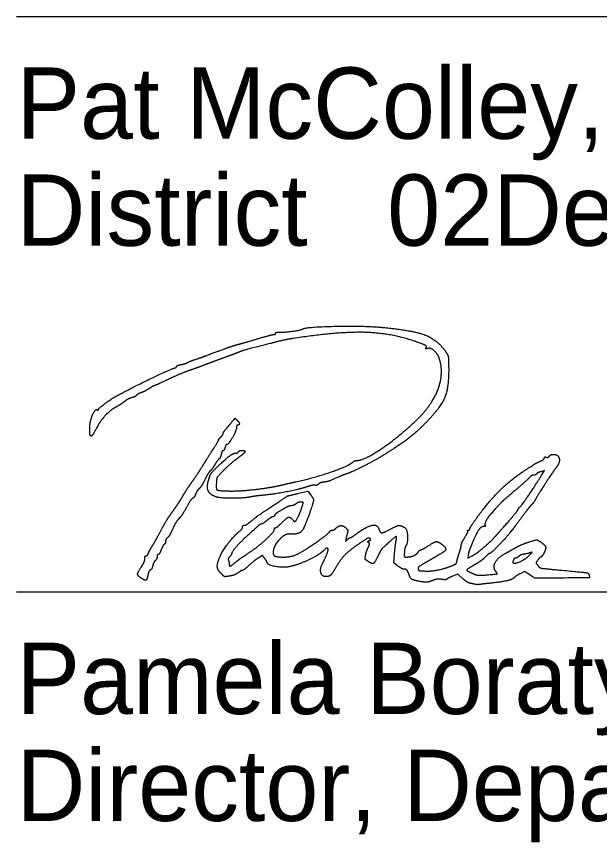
# Model space of a CAD drawing. Extents: x 0 to 34, y 0 to 22.
# Drawn here: x 24.528 to 25.673, y 7.305 to 8.926 of the extents above; entities that cross this region are included whole.
import ezdxf

# ---------------------------------------------------------------- set-up
doc = ezdxf.new("R2010")
doc.units = 0
doc.layers.add('SH_Data', color=7, linetype='Continuous')
doc.layers.add('SH_Text', color=7, linetype='Continuous')

msp = doc.modelspace()

# ---------------------------------------------------------------- linework, layer by layer
at = {"layer": 'SH_Data'}
for p, q in [((24.5279, 8.9262), (28.0279, 8.9262)), ((24.5279, 7.7968), (28.0279, 7.7968))]:
    msp.add_line(p, q, dxfattribs=at)
at = {"layer": 'SH_Text'}
for points in [[(25.5597, 8.0263), (25.5651, 8.0352), (25.5577, 8.0326)], [(25.0824, 7.9901), (25.1004, 7.9942), (25.1051, 7.988)], [(25.2773, 7.8473), (25.269, 7.8536), (25.2704, 7.8707)], [(25.4153, 7.8693), (25.4143, 7.8628), (25.4229, 7.8673)], [(25.5361, 7.83), (25.5255, 7.8368), (25.5171, 7.8323)], [(25.4043, 7.823), (25.3951, 7.8313), (25.3845, 7.8272)]]:
    msp.add_lwpolyline(points, dxfattribs=at)
for points in [[(25.033, 8.3018), (25.0351, 8.3018), (25.0368, 8.3029), (25.0368, 8.3043)], [(25.0368, 8.3043), (25.0368, 8.3056), (25.0408, 8.3066), (25.0458, 8.3065)], [(25.0458, 8.3065), (25.0554, 8.3062), (25.0864, 8.3106), (25.0898, 8.3127)], [(25.3205, 8.285), (25.2699, 8.304), (25.1619, 8.308), (25.0716, 8.2942)], [(25.0898, 8.3127), (25.0966, 8.3169), (25.2136, 8.3192), (25.248, 8.3158)], [(25.248, 8.3158), (25.3072, 8.31), (25.3548, 8.2917), (25.3706, 8.2686)], [(24.9612, 8.282), (24.9665, 8.2833), (24.9839, 8.2883), (25, 8.2931)], [(25, 8.2931), (25.0161, 8.2979), (25.031, 8.3018), (25.033, 8.3018)], [(25.0716, 8.2942), (25.0623, 8.2928), (25.0424, 8.2885), (25.0272, 8.2845)], [(24.8808, 8.2535), (24.8955, 8.2586), (24.9019, 8.261), (24.9372, 8.2741)], [(24.9372, 8.2741), (24.9451, 8.2771), (24.9559, 8.2806), (24.9612, 8.282)], [(25.0272, 8.2845), (24.9762, 8.2714), (24.9719, 8.2701), (24.9612, 8.2658)], [(25.3328, 8.2764), (25.3338, 8.2789), (25.3303, 8.2813), (25.3205, 8.285)], [(25.3352, 8.2743), (25.3326, 8.2733), (25.3319, 8.274), (25.3328, 8.2764)], [(25.3586, 8.2544), (25.3553, 8.2642), (25.3409, 8.2765), (25.3352, 8.2743)], [(24.9384, 8.2573), (24.9285, 8.2537), (24.9134, 8.2481), (24.9048, 8.2449)], [(24.9612, 8.2658), (24.9585, 8.2647), (24.9483, 8.2609), (24.9384, 8.2573)], [(25.3131, 8.1332), (25.344, 8.1627), (25.3679, 8.2262), (25.3586, 8.2544)], [(25.3706, 8.2686), (25.3755, 8.2614), (25.3764, 8.257), (25.3768, 8.2392)], [(24.837, 8.2357), (24.84, 8.2366), (24.8424, 8.2382), (24.8424, 8.2393)], [(24.8424, 8.2393), (24.8424, 8.2403), (24.8464, 8.242), (24.8514, 8.2429)], [(24.8514, 8.2429), (24.8563, 8.2438), (24.8615, 8.2454), (24.8628, 8.2464)], [(24.8628, 8.2464), (24.8641, 8.2473), (24.8722, 8.2506), (24.8808, 8.2535)], [(24.9048, 8.2449), (24.8962, 8.2416), (24.88, 8.2357), (24.8688, 8.2317)], [(25.3768, 8.2392), (25.3775, 8.1984), (25.3614, 8.1587), (25.332, 8.1288)], [(24.7248, 8.1814), (24.755, 8.1976), (24.8286, 8.2333), (24.837, 8.2357)], [(24.8688, 8.2317), (24.8576, 8.2278), (24.8372, 8.2192), (24.8236, 8.2127)], [(24.8236, 8.2127), (24.8099, 8.2063), (24.7983, 8.201), (24.7977, 8.201)], [(24.7877, 8.1953), (24.7828, 8.1922), (24.7761, 8.1888), (24.7729, 8.1878)], [(24.7977, 8.201), (24.7971, 8.201), (24.7927, 8.1984), (24.7877, 8.1953)], [(24.6888, 8.1547), (24.6888, 8.1569), (24.7142, 8.1757), (24.7248, 8.1814)], [(24.754, 8.1778), (24.7505, 8.1769), (24.7438, 8.1733), (24.7392, 8.1697)], [(24.7637, 8.1826), (24.7619, 8.1808), (24.7576, 8.1787), (24.754, 8.1778)], [(24.7729, 8.1878), (24.7697, 8.1868), (24.7655, 8.1844), (24.7637, 8.1826)], [(24.7233, 8.1594), (24.7129, 8.1541), (24.693, 8.1332), (24.6868, 8.1211)], [(24.7392, 8.1697), (24.7346, 8.1661), (24.7274, 8.1615), (24.7233, 8.1594)], [(24.6716, 8.1169), (24.6717, 8.1301), (24.6823, 8.1567), (24.6865, 8.1541)], [(24.6865, 8.1541), (24.6877, 8.1533), (24.6888, 8.1536), (24.6888, 8.1547)], [(24.939, 8.1158), (24.9575, 8.1379), (24.9568, 8.1374), (24.9609, 8.134)], [(24.9609, 8.134), (24.9652, 8.1304), (24.9661, 8.1242), (24.9624, 8.1242)], [(25.1964, 8.0546), (25.2105, 8.0546), (25.2786, 8.1005), (25.3131, 8.1332)], [(25.332, 8.1288), (25.3134, 8.1099), (25.281, 8.085), (25.2505, 8.0662)], [(24.673, 8.1032), (24.6722, 8.104), (24.6716, 8.1101), (24.6716, 8.1169)], [(24.6868, 8.1211), (24.6801, 8.1082), (24.6748, 8.1013), (24.673, 8.1032)], [(24.9336, 8.1072), (24.9336, 8.1084), (24.936, 8.1123), (24.939, 8.1158)], [(24.96, 8.1191), (24.96, 8.1135), (24.9441, 8.0858), (24.9409, 8.0858)], [(24.9624, 8.1242), (24.9611, 8.1242), (24.96, 8.1219), (24.96, 8.1191)], [(24.916, 8.0797), (24.9216, 8.0883), (24.9256, 8.0954), (24.925, 8.0954)], [(24.925, 8.0954), (24.9245, 8.0954), (24.9261, 8.0975), (24.9288, 8.1002)], [(24.9288, 8.1002), (24.9314, 8.1028), (24.9336, 8.1059), (24.9336, 8.1072)], [(24.894, 8.0447), (24.9006, 8.0553), (24.9105, 8.0711), (24.916, 8.0797)], [(24.9374, 8.0798), (24.9366, 8.0765), (24.9349, 8.0738), (24.9337, 8.0738)], [(24.9409, 8.0858), (24.9398, 8.0858), (24.9382, 8.0831), (24.9374, 8.0798)], [(24.9252, 8.0448), (24.9409, 8.0594), (24.9536, 8.069), (24.9576, 8.069)], [(24.93, 8.0666), (24.9291, 8.0626), (24.9274, 8.0588), (24.9261, 8.058)], [(24.9337, 8.0738), (24.9325, 8.0738), (24.9309, 8.0705), (24.93, 8.0666)], [(24.9576, 8.069), (24.9601, 8.069), (24.9628, 8.07), (24.9636, 8.0714)], [(24.9768, 8.0717), (24.9768, 8.0706), (24.97, 8.0647), (24.9618, 8.0586)], [(24.9636, 8.0714), (24.9654, 8.0743), (24.9768, 8.0746), (24.9768, 8.0717)], [(25.2505, 8.0662), (25.2313, 8.0543), (25.1901, 8.0333), (25.176, 8.0282)], [(25.5648, 8.0595), (25.5648, 8.061), (25.5663, 8.0617), (25.5682, 8.061)], [(25.5682, 8.061), (25.5701, 8.0602), (25.5729, 8.0612), (25.5745, 8.0631)], [(25.5745, 8.0631), (25.5761, 8.065), (25.5798, 8.0666), (25.5827, 8.0666)], [(25.5827, 8.0666), (25.5921, 8.0666), (25.5959, 8.0505), (25.5885, 8.0415)], [(24.8722, 8.0117), (24.8776, 8.0192), (24.8874, 8.034), (24.894, 8.0447)], [(24.9038, 8.0102), (24.9066, 8.0232), (24.9127, 8.0332), (24.9252, 8.0448)], [(24.9176, 8.0466), (24.9142, 8.0411), (24.9101, 8.0355), (24.9084, 8.0341)], [(24.9261, 8.058), (24.9248, 8.0572), (24.921, 8.0521), (24.9176, 8.0466)], [(24.9618, 8.0586), (24.9535, 8.0525), (24.941, 8.0416), (24.934, 8.0345)], [(25.0764, 8.0126), (25.1133, 8.0208), (25.1796, 8.0437), (25.1882, 8.0512)], [(25.1882, 8.0512), (25.1903, 8.0531), (25.1939, 8.0546), (25.1964, 8.0546)], [(25.528, 8.0362), (25.5469, 8.0484), (25.5488, 8.0495), (25.557, 8.0532)], [(25.557, 8.0532), (25.5613, 8.0551), (25.5648, 8.058), (25.5648, 8.0595)], [(24.9084, 8.0341), (24.9068, 8.0328), (24.9021, 8.0252), (24.8981, 8.0172)], [(24.934, 8.0345), (24.9233, 8.0235), (24.9211, 8.0199), (24.9206, 8.0116)], [(25.176, 8.0282), (25.1714, 8.0266), (25.1643, 8.0238), (25.1603, 8.022)], [(25.4334, 7.9437), (25.4556, 7.9745), (25.5007, 8.0185), (25.528, 8.0362)], [(25.549, 8.0279), (25.5483, 8.0267), (25.5459, 8.0258), (25.5437, 8.0258)], [(25.5885, 8.0415), (25.5843, 8.0365), (25.5515, 7.9861), (25.5483, 7.9799)], [(25.5577, 8.0326), (25.5537, 8.0312), (25.5498, 8.0291), (25.549, 8.0279)], [(24.8555, 7.9862), (24.8593, 7.9928), (24.8669, 8.0043), (24.8722, 8.0117)], [(24.8981, 8.0172), (24.8941, 8.0092), (24.889, 8.0012), (24.8868, 7.9994)], [(24.9206, 8.0116), (24.9197, 7.9982), (24.9238, 7.9953), (24.9444, 7.9947)], [(25.0428, 8.0051), (25.0507, 8.0069), (25.0658, 8.0103), (25.0764, 8.0126)], [(25.1318, 8.0121), (25.1279, 8.0117), (25.123, 8.0099), (25.121, 8.0081)], [(25.1603, 8.022), (25.1433, 8.0146), (25.1384, 8.0129), (25.1318, 8.0121)], [(25.5349, 8.0204), (25.5322, 8.0174), (25.5197, 8.0063), (25.5072, 7.9958)], [(25.5169, 7.9634), (25.5197, 7.9653), (25.5479, 8.0068), (25.5597, 8.0263)], [(25.5437, 8.0258), (25.5415, 8.0258), (25.5375, 8.0233), (25.5349, 8.0204)], [(24.8868, 7.9994), (24.8847, 7.9976), (24.8814, 7.9925), (24.8796, 7.9881)], [(24.9192, 7.9833), (24.9087, 7.9872), (24.9016, 7.9997), (24.9038, 8.0102)], [(24.9444, 7.9947), (24.9636, 7.9942), (25.0215, 8.0003), (25.0428, 8.0051)], [(25.0962, 8.0022), (25.0797, 7.9969), (25.0346, 7.9884), (25.0108, 7.9861)], [(25.1142, 8.0059), (25.1125, 8.0065), (25.1044, 8.0048), (25.0962, 8.0022)], [(25.121, 8.0081), (25.1189, 8.0063), (25.1158, 8.0053), (25.1142, 8.0059)], [(25.5072, 7.9958), (25.4876, 7.9793), (25.4759, 7.9679), (25.4592, 7.949)], [(24.8425, 7.9655), (24.8458, 7.9703), (24.8517, 7.9796), (24.8555, 7.9862)], [(24.8739, 7.9802), (24.8726, 7.9802), (24.8672, 7.9723), (24.8618, 7.9626)], [(24.8796, 7.9881), (24.8777, 7.9838), (24.8752, 7.9802), (24.8739, 7.9802)], [(24.9904, 7.9835), (24.9767, 7.9804), (24.9272, 7.9803), (24.9192, 7.9833)], [(25.0108, 7.9861), (25.0025, 7.9853), (24.9933, 7.9841), (24.9904, 7.9835)], [(25.0284, 7.9637), (25.06, 7.9847), (25.0614, 7.9854), (25.0824, 7.9901)], [(25.1051, 7.988), (25.1117, 7.9792), (25.1115, 7.9744), (25.1038, 7.9518)], [(25.5483, 7.9799), (25.5466, 7.9764), (25.5427, 7.971), (25.5397, 7.9678)], [(24.8289, 7.9463), (24.833, 7.9521), (24.8391, 7.9608), (24.8425, 7.9655)], [(24.8618, 7.9626), (24.8565, 7.9529), (24.8498, 7.9429), (24.847, 7.9404)], [(24.9892, 7.9358), (25.0029, 7.9468), (25.0009, 7.9455), (25.0284, 7.9637)], [(25.0581, 7.9626), (25.0436, 7.9547), (25.0344, 7.9483), (25.0344, 7.9463)], [(25.0678, 7.9658), (25.0656, 7.9658), (25.0612, 7.9643), (25.0581, 7.9626)], [(25.0765, 7.9693), (25.074, 7.9673), (25.07, 7.9658), (25.0678, 7.9658)], [(25.075, 7.9346), (25.0768, 7.9346), (25.0866, 7.9557), (25.0897, 7.9664)], [(25.0864, 7.9729), (25.0835, 7.9728), (25.0791, 7.9712), (25.0765, 7.9693)], [(25.0897, 7.9664), (25.0914, 7.9721), (25.091, 7.9729), (25.0864, 7.9729)], [(25.513, 7.9582), (25.5142, 7.9604), (25.5159, 7.9627), (25.5169, 7.9634)], [(25.5397, 7.9678), (25.5367, 7.9645), (25.5278, 7.9532), (25.5199, 7.9425)], [(24.81, 7.9142), (24.8163, 7.926), (24.8248, 7.9405), (24.8289, 7.9463)], [(25.0344, 7.9463), (25.0344, 7.9451), (25.0332, 7.9442), (25.0317, 7.9442)], [(25.1038, 7.9518), (25.0935, 7.9219), (25.0815, 7.9088), (25.0656, 7.9102)], [(25.4592, 7.949), (25.4533, 7.9424), (25.4471, 7.9295), (25.4485, 7.9271)], [(25.4817, 7.9204), (25.497, 7.9375), (25.5106, 7.9539), (25.513, 7.9582)], [(24.847, 7.9404), (24.8441, 7.9378), (24.8386, 7.9287), (24.8347, 7.9202)], [(24.9754, 7.9274), (24.9772, 7.9274), (24.9834, 7.9311), (24.9892, 7.9358)], [(25.02, 7.937), (25.015, 7.933), (25.01, 7.9298), (25.0088, 7.9297)], [(25.0317, 7.9442), (25.0303, 7.9442), (25.025, 7.9409), (25.02, 7.937)], [(25.0368, 7.9226), (25.0381, 7.9226), (25.0435, 7.9269), (25.0488, 7.9322)], [(25.0488, 7.9322), (25.0589, 7.9423), (25.0654, 7.9441), (25.0704, 7.9382)], [(25.0704, 7.9382), (25.072, 7.9362), (25.0741, 7.9346), (25.075, 7.9346)], [(25.4184, 7.9203), (25.4184, 7.9217), (25.4251, 7.9322), (25.4334, 7.9437)], [(25.5199, 7.9425), (25.512, 7.9319), (25.5043, 7.9217), (25.5029, 7.9199)], [(24.7946, 7.8866), (24.7968, 7.8899), (24.8037, 7.9023), (24.81, 7.9142)], [(24.8347, 7.9202), (24.8307, 7.9116), (24.826, 7.9037), (24.8242, 7.9026)], [(24.9285, 7.8679), (24.933, 7.8783), (24.9562, 7.9078), (24.9666, 7.9161)], [(24.9666, 7.9161), (24.9695, 7.9185), (24.972, 7.922), (24.972, 7.9239)], [(24.972, 7.9239), (24.972, 7.9258), (24.9735, 7.9274), (24.9754, 7.9274)], [(25.0088, 7.9297), (25.0069, 7.9297), (24.9985, 7.9225), (24.9732, 7.8992)], [(24.9883, 7.876), (25.0039, 7.8864), (25.0344, 7.9151), (25.0344, 7.9194)], [(25.0344, 7.9194), (25.0344, 7.9212), (25.0355, 7.9226), (25.0368, 7.9226)], [(25.1004, 7.8829), (25.119, 7.8953), (25.1414, 7.9119), (25.1431, 7.9147)], [(25.1431, 7.9147), (25.1442, 7.9164), (25.1465, 7.9178), (25.1483, 7.9178)], [(25.1483, 7.9178), (25.1501, 7.9178), (25.1534, 7.9195), (25.1555, 7.9217)], [(25.1555, 7.9217), (25.1605, 7.9266), (25.1705, 7.9267), (25.1754, 7.9217)], [(25.1754, 7.9217), (25.1786, 7.9186), (25.1788, 7.9161), (25.1767, 7.907)], [(25.1935, 7.9091), (25.2138, 7.9243), (25.2365, 7.9299), (25.2395, 7.9204)], [(25.2395, 7.9204), (25.2419, 7.9128), (25.25, 7.9127), (25.2633, 7.9201)], [(25.2633, 7.9201), (25.2752, 7.9267), (25.2825, 7.9274), (25.2907, 7.9228)], [(25.2907, 7.9228), (25.2951, 7.9203), (25.2967, 7.8923), (25.2928, 7.8872)], [(25.4086, 7.9035), (25.4125, 7.9097), (25.415, 7.9155), (25.4142, 7.9163)], [(25.4142, 7.9163), (25.4134, 7.9171), (25.414, 7.9178), (25.4156, 7.9178)], [(25.4156, 7.9178), (25.4171, 7.9178), (25.4184, 7.9189), (25.4184, 7.9203)], [(25.4462, 7.925), (25.4399, 7.925), (25.4304, 7.9098), (25.4183, 7.8806)], [(25.4485, 7.9271), (25.4493, 7.9259), (25.4482, 7.925), (25.4462, 7.925)], [(25.4661, 7.9029), (25.4692, 7.9065), (25.4762, 7.9143), (25.4817, 7.9204)], [(25.5029, 7.9199), (25.4896, 7.9034), (25.485, 7.8983), (25.4732, 7.8861)], [(24.8242, 7.9026), (24.8223, 7.9016), (24.8208, 7.8987), (24.8208, 7.8962)], [(24.9732, 7.8992), (24.9641, 7.8909), (24.9504, 7.8738), (24.9504, 7.8708)], [(25.0656, 7.9102), (25.0552, 7.9111), (25.032, 7.8857), (25.032, 7.8735)], [(25.1767, 7.907), (25.1744, 7.8967), (25.1745, 7.8962), (25.1783, 7.8997)], [(25.1783, 7.8997), (25.1805, 7.9017), (25.1832, 7.9034), (25.1841, 7.9034)], [(25.1841, 7.9034), (25.1851, 7.9034), (25.1893, 7.9059), (25.1935, 7.9091)], [(25.2222, 7.9013), (25.2204, 7.9031), (25.2145, 7.9003), (25.202, 7.8918)], [(25.2206, 7.8971), (25.2236, 7.8982), (25.224, 7.8995), (25.2222, 7.9013)], [(25.2734, 7.8956), (25.2752, 7.905), (25.2726, 7.9054), (25.2633, 7.8972)], [(25.4016, 7.8887), (25.4016, 7.8905), (25.4047, 7.8972), (25.4086, 7.9035)], [(25.446, 7.8841), (25.4539, 7.8909), (25.4629, 7.8994), (25.4661, 7.9029)], [(25.5353, 7.8948), (25.5493, 7.899), (25.5505, 7.899), (25.5564, 7.8952)], [(24.7877, 7.874), (24.7893, 7.8776), (24.7924, 7.8833), (24.7946, 7.8866)], [(24.8183, 7.8901), (24.8169, 7.8892), (24.8141, 7.8843), (24.812, 7.8792)], [(24.8208, 7.8962), (24.8208, 7.8937), (24.8197, 7.8909), (24.8183, 7.8901)], [(25.0519, 7.865), (25.065, 7.865), (25.0841, 7.872), (25.1004, 7.8829)], [(25.14, 7.8797), (25.14, 7.8827), (25.136, 7.8822), (25.1324, 7.8787)], [(25.202, 7.8918), (25.1823, 7.8784), (25.1651, 7.8613), (25.1568, 7.847)], [(25.2136, 7.8682), (25.2144, 7.8723), (25.2166, 7.8794), (25.2187, 7.8838)], [(25.2194, 7.8936), (25.2172, 7.895), (25.2175, 7.8959), (25.2206, 7.8971)], [(25.2187, 7.8838), (25.2215, 7.8901), (25.2217, 7.8922), (25.2194, 7.8936)], [(25.2633, 7.8972), (25.2474, 7.8832), (25.2437, 7.8788), (25.2382, 7.8674)], [(25.2704, 7.8707), (25.2712, 7.8801), (25.2726, 7.8913), (25.2734, 7.8956)], [(25.2928, 7.8872), (25.2916, 7.8855), (25.2903, 7.8798), (25.2899, 7.8746)], [(25.3224, 7.8794), (25.3236, 7.8794), (25.3297, 7.8826), (25.336, 7.8866)], [(25.3642, 7.8895), (25.3739, 7.8819), (25.367, 7.874), (25.3354, 7.8563)], [(25.336, 7.8866), (25.3489, 7.8948), (25.3565, 7.8956), (25.3642, 7.8895)], [(25.3981, 7.8746), (25.4, 7.8805), (25.4016, 7.8869), (25.4016, 7.8887)], [(25.4229, 7.8673), (25.4277, 7.8697), (25.4381, 7.8773), (25.446, 7.8841)], [(25.4732, 7.8861), (25.4657, 7.8784), (25.4586, 7.8722), (25.4576, 7.8722)], [(25.4864, 7.8711), (25.4893, 7.8726), (25.4981, 7.8776), (25.506, 7.8821)], [(25.506, 7.8821), (25.5139, 7.8866), (25.5271, 7.8923), (25.5353, 7.8948)], [(25.5564, 7.8952), (25.566, 7.8889), (25.5684, 7.8815), (25.5638, 7.8725)], [(24.78, 7.8617), (24.78, 7.8648), (24.7811, 7.8674), (24.7824, 7.8674)], [(24.7824, 7.8674), (24.7838, 7.8674), (24.7862, 7.8703), (24.7877, 7.874)], [(24.804, 7.8653), (24.804, 7.8628), (24.8024, 7.8595), (24.8005, 7.8579)], [(24.8061, 7.8698), (24.8049, 7.8698), (24.804, 7.8677), (24.804, 7.8653)], [(24.812, 7.8792), (24.81, 7.874), (24.8073, 7.8698), (24.8061, 7.8698)], [(24.9302, 7.8322), (24.9225, 7.8398), (24.9219, 7.8526), (24.9285, 7.8679)], [(24.9466, 7.8657), (24.9446, 7.8636), (24.9435, 7.8604), (24.9442, 7.8585)], [(24.9504, 7.8708), (24.9504, 7.87), (24.9487, 7.8677), (24.9466, 7.8657)], [(24.9568, 7.8536), (24.9643, 7.8597), (24.9696, 7.8635), (24.9883, 7.876)], [(25.0154, 7.8624), (25.0109, 7.8682), (25.0108, 7.8682), (25.0041, 7.8638)], [(25.032, 7.8735), (25.032, 7.8683), (25.0398, 7.865), (25.0519, 7.865)], [(25.1324, 7.8787), (25.1228, 7.8696), (25.084, 7.8508), (25.0656, 7.8463)], [(25.1294, 7.853), (25.1335, 7.8606), (25.14, 7.8769), (25.14, 7.8797)], [(25.2182, 7.8566), (25.2132, 7.8599), (25.2124, 7.8619), (25.2136, 7.8682)], [(25.2382, 7.8674), (25.2315, 7.8537), (25.2267, 7.8511), (25.2182, 7.8566)], [(25.2899, 7.8746), (25.2894, 7.867), (25.2901, 7.865), (25.2932, 7.865)], [(25.2932, 7.865), (25.3016, 7.865), (25.3136, 7.8698), (25.3168, 7.8745)], [(25.3168, 7.8745), (25.3187, 7.8772), (25.3212, 7.8794), (25.3224, 7.8794)], [(25.3933, 7.8575), (25.394, 7.8609), (25.3961, 7.8686), (25.3981, 7.8746)], [(25.4183, 7.8806), (25.4172, 7.8779), (25.4159, 7.8728), (25.4153, 7.8693)], [(25.449, 7.8652), (25.4454, 7.8614), (25.4373, 7.8553), (25.431, 7.8516)], [(25.4576, 7.8722), (25.4565, 7.8722), (25.4526, 7.869), (25.449, 7.8652)], [(25.4694, 7.8367), (25.4633, 7.8441), (25.4731, 7.8639), (25.4864, 7.8711)], [(25.5033, 7.8568), (25.5008, 7.8503), (25.5263, 7.8593), (25.5348, 7.8679)], [(25.5144, 7.8662), (25.5122, 7.8642), (25.5091, 7.8626), (25.5076, 7.8626)], [(25.5254, 7.8707), (25.5215, 7.8702), (25.5166, 7.8681), (25.5144, 7.8662)], [(25.5372, 7.8734), (25.5345, 7.8724), (25.5292, 7.8712), (25.5254, 7.8707)], [(25.5348, 7.8679), (25.5403, 7.8735), (25.5408, 7.8748), (25.5372, 7.8734)], [(25.5638, 7.8725), (25.5616, 7.8683), (25.5589, 7.865), (25.5578, 7.865)], [(24.7742, 7.8475), (24.7774, 7.8522), (24.78, 7.8586), (24.78, 7.8617)], [(24.8005, 7.8579), (24.7986, 7.8563), (24.7964, 7.8518), (24.7955, 7.8478)], [(24.9442, 7.8585), (24.945, 7.8565), (24.9456, 7.8534), (24.9456, 7.8516)], [(24.9456, 7.8516), (24.9456, 7.8467), (24.949, 7.8473), (24.9568, 7.8536)], [(25.0041, 7.8638), (24.9959, 7.8584), (24.9933, 7.8564), (24.9821, 7.8464)], [(25.0199, 7.855), (25.0199, 7.8559), (25.0179, 7.8592), (25.0154, 7.8624)], [(25.0656, 7.8463), (25.0527, 7.8433), (25.0201, 7.8494), (25.0199, 7.855)], [(25.1361, 7.8266), (25.1277, 7.8266), (25.1237, 7.8424), (25.1294, 7.853)], [(25.3354, 7.8563), (25.3222, 7.8488), (25.316, 7.844), (25.3168, 7.8418)], [(25.3806, 7.8469), (25.3894, 7.8502), (25.3923, 7.8527), (25.3933, 7.8575)], [(25.431, 7.8516), (25.4131, 7.8412), (25.412, 7.8379), (25.425, 7.8324)], [(25.5048, 7.8616), (25.5048, 7.861), (25.5041, 7.8589), (25.5033, 7.8568)], [(25.5076, 7.8626), (25.506, 7.8626), (25.5048, 7.8621), (25.5048, 7.8616)], [(25.5519, 7.8591), (25.5484, 7.8538), (25.5484, 7.8529), (25.5523, 7.8482)], [(25.5578, 7.865), (25.5567, 7.865), (25.554, 7.8623), (25.5519, 7.8591)], [(24.7725, 7.8238), (24.7655, 7.8286), (24.7659, 7.8354), (24.7742, 7.8475)], [(24.7908, 7.8394), (24.7891, 7.8388), (24.787, 7.8346), (24.7862, 7.8302)], [(24.7955, 7.8478), (24.7946, 7.8439), (24.7925, 7.8401), (24.7908, 7.8394)], [(24.9629, 7.8338), (24.9593, 7.8312), (24.9519, 7.8284), (24.9464, 7.8276)], [(24.9714, 7.8386), (24.9703, 7.8386), (24.9665, 7.8364), (24.9629, 7.8338)], [(24.9821, 7.8464), (24.9773, 7.8421), (24.9725, 7.8386), (24.9714, 7.8386)], [(25.1568, 7.847), (25.1486, 7.8329), (25.1422, 7.8266), (25.1361, 7.8266)], [(25.2903, 7.841), (25.2877, 7.841), (25.2819, 7.8438), (25.2773, 7.8473)], [(25.2978, 7.8332), (25.296, 7.8383), (25.2934, 7.841), (25.2903, 7.841)], [(25.3232, 7.8166), (25.3082, 7.819), (25.3013, 7.8235), (25.2978, 7.8332)], [(25.3168, 7.8418), (25.3181, 7.8384), (25.3188, 7.8382), (25.3308, 7.8375)], [(25.3308, 7.8375), (25.3413, 7.8369), (25.3674, 7.8418), (25.3806, 7.8469)], [(25.4518, 7.8299), (25.4713, 7.8315), (25.4731, 7.8322), (25.4694, 7.8367)], [(25.5523, 7.8482), (25.5559, 7.8437), (25.5609, 7.8427), (25.5948, 7.8395)], [(25.5948, 7.8395), (25.6439, 7.835), (25.6521, 7.8334), (25.6531, 7.8287)], [(24.7862, 7.8302), (24.7843, 7.8205), (24.7801, 7.8185), (24.7725, 7.8238)], [(24.9464, 7.8276), (24.9377, 7.8262), (24.9355, 7.8268), (24.9302, 7.8322)], [(25.3443, 7.8186), (25.3373, 7.8158), (25.3318, 7.8153), (25.3232, 7.8166)], [(25.3632, 7.8211), (25.3574, 7.8219), (25.3501, 7.8209), (25.3443, 7.8186)], [(25.3733, 7.8215), (25.3729, 7.8206), (25.3683, 7.8204), (25.3632, 7.8211)], [(25.3845, 7.8272), (25.3787, 7.8249), (25.3737, 7.8224), (25.3733, 7.8215)], [(25.4189, 7.8135), (25.4159, 7.8142), (25.4093, 7.8184), (25.4043, 7.823)], [(25.425, 7.8324), (25.4318, 7.8294), (25.4383, 7.8289), (25.4518, 7.8299)], [(25.5054, 7.8244), (25.5017, 7.8207), (25.4802, 7.8158), (25.4568, 7.8134)], [(25.5171, 7.8323), (25.5125, 7.8298), (25.5072, 7.8263), (25.5054, 7.8244)], [(25.5828, 7.8236), (25.5471, 7.8232), (25.5467, 7.8232), (25.5361, 7.83)], [(25.6531, 7.8287), (25.6539, 7.8244), (25.6519, 7.8243), (25.5828, 7.8236)], [(25.4292, 7.8114), (25.4265, 7.8119), (25.4219, 7.8129), (25.4189, 7.8135)], [(25.4376, 7.8111), (25.4356, 7.8107), (25.4318, 7.8108), (25.4292, 7.8114)], [(25.4568, 7.8134), (25.4482, 7.8125), (25.4396, 7.8115), (25.4376, 7.8111)]]:
    msp.add_open_spline(points, degree=2, dxfattribs=at)

# ---------------------------------------------------------------- texts
for s, p in [('Pat McColley, P.E., S.I.', (24.5279, 8.6862)), ('District       Deputy Director', (24.5279, 8.4762)), ('              02', (24.5279, 8.4762)), ('Pamela Boratyn', (24.5279, 7.5568)), ('Director, Department of Transportation', (24.5279, 7.3468))]:
    msp.add_text(s, height=0.14, dxfattribs=at).set_placement(p)

doc.saveas('drawing.dxf')
